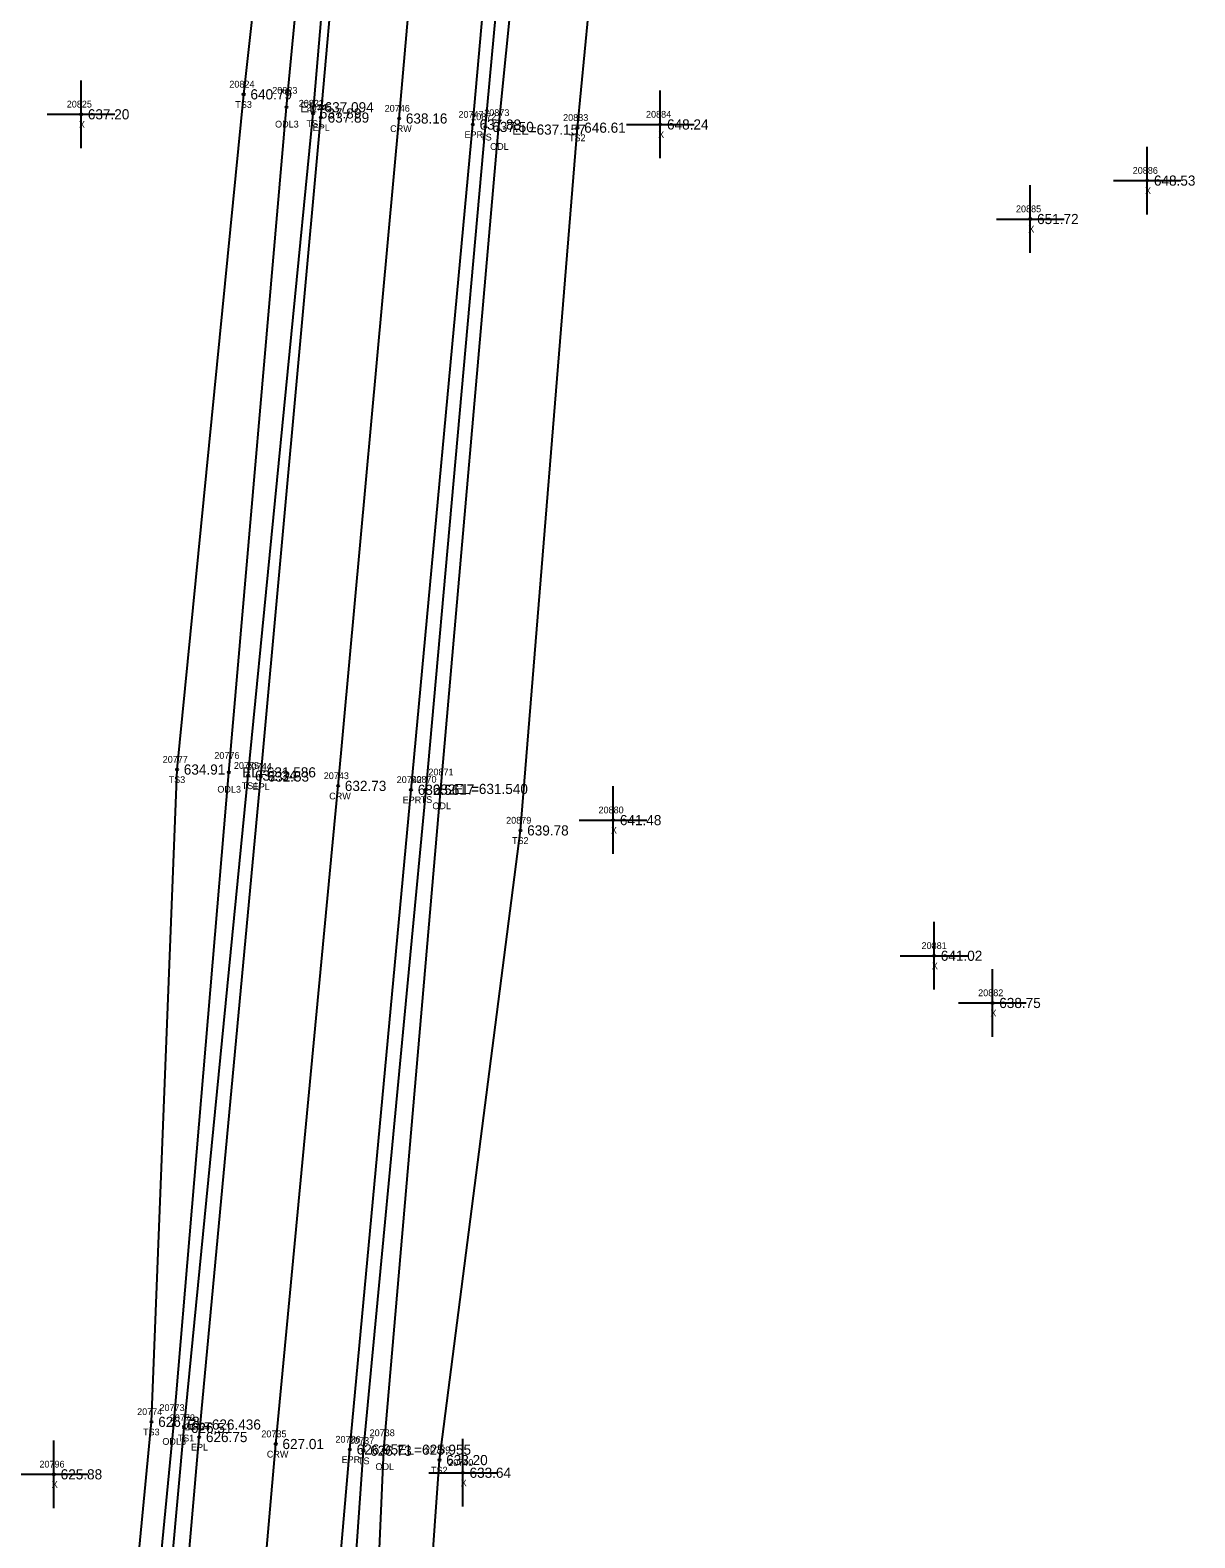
# Model space of a CAD drawing. Extents: x 1695443 to 1696344, y 1087542 to 1090645.
# Drawn here: x 1695816.3 to 1695988.4, y 1090201.9 to 1090424.7 of the extents above; entities that cross this region are included whole.
import ezdxf

# ---------------------------------------------------------------- set-up
doc = ezdxf.new("R2010")
doc.units = 0
for name, color, linetype in [('RD_DTM_BkLn1', 7, 'Continuous'), ('RD_DTM_BkLn2', 7, 'Continuous'), ('RD_DTM_BkLn_txCode', 7, 'Continuous'), ('RD_EX_H2O', 7, 'Continuous'), ('RD_EX_H2O_txCode', 7, 'Continuous'), ('RD_EX_Misc', 7, 'Continuous'), ('RD_EX_Misc_txCode', 7, 'Continuous'), ('RD_EX_Road', 7, 'Continuous'), ('RD_EX_Road_txCode', 7, 'Continuous'), ('RD_EX_TX_H2O_ELEV', 7, 'Continuous'), ('RD_EX_TX_Misc_ELEV', 7, 'Continuous'), ('RD_EX_TX_Road_ELEV', 7, 'Continuous'), ('RD_HC_Survey_ELEV', 7, 'Continuous'), ('RD_HC_Survey_txCode', 7, 'Continuous'), ('RD_SMD_Locator', 7, 'Continuous')]:
    doc.layers.add(name, color=color, linetype=linetype)

msp = doc.modelspace()

# ---------------------------------------------------------------- linework, layer by layer
at = {"layer": 'RD_DTM_BkLn1'}
msp.add_lwpolyline([(1695813.78, 1089148.1), (1695785.55, 1089189.03), (1695758.89, 1089235.87), (1695740.64, 1089279.02), (1695725.17, 1089334.02), (1695718.27, 1089382.65), (1695717.41, 1089435.13), (1695722.03, 1089482.62), (1695732.64, 1089534.75), (1695759.85, 1089631.43), (1695787.11, 1089727.89), (1695798.89, 1089774.41), (1695810.31, 1089824.5), (1695818.49, 1089870.61), (1695825.85, 1089922.33), (1695831.69, 1089976.57), (1695835.49, 1090019.27), (1695844.06, 1090117.91), (1695852.56, 1090215.73), (1695861.78, 1090313.02), (1695870.8, 1090411.68), (1695879.44, 1090510.15), (1695888.04, 1090606.94)], dxfattribs=at)
at = {"layer": 'RD_DTM_BkLn2'}
for points in [[(1695816.55, 1089985.57), (1695822.06, 1090019.33), (1695830.08, 1090118.98), (1695839.03, 1090218.11), (1695848.5, 1090314.54), (1695858.08, 1090412.43), (1695866.47, 1090510.6), (1695872.4, 1090582.09), (1695875.15, 1090613.95)], [(1695859.8, 1090070.52), (1695855.89, 1090074.82), (1695858.76, 1090117.78), (1695865.52, 1090214.74), (1695874.78, 1090312.49), (1695883.57, 1090410.43), (1695892.81, 1090510.92), (1695900.47, 1090609.03)], [(1695859.8, 1090070.52), (1695863.31, 1090073.64), (1695869.86, 1090116.28), (1695876.76, 1090213.36), (1695888.73, 1090306.44), (1695897.16, 1090410.32), (1695906.91, 1090511.46), (1695912.67, 1090607.68)], [(1695816.55, 1089985.57), (1695816.58, 1090019.89), (1695824.64, 1090119.16), (1695834.2, 1090219.01), (1695837.98, 1090315.44), (1695847.83, 1090415.25), (1695858.61, 1090512.14), (1695862.95, 1090562.02), (1695858.41, 1090574.71)]]:
    msp.add_lwpolyline(points, dxfattribs=at)
at = {"layer": 'RD_EX_H2O'}
for points in [[(1695860.52, 1090075.19), (1695864.26, 1090116.99), (1695868.56, 1090214.89), (1695876.96, 1090312.57), (1695885.5, 1090410.04), (1695895.53, 1090510.16), (1695905.88, 1090602.7), (1695906.59, 1090606.36)], [(1695816.55, 1089985.57), (1695820.09, 1090019.62), (1695827.87, 1090118.57), (1695837.5, 1090218.61), (1695845.63, 1090315.02), (1695854.17, 1090413.34), (1695863.46, 1090511.07), (1695865.97, 1090562.3), (1695858.41, 1090574.71)]]:
    msp.add_lwpolyline(points, dxfattribs=at)
at = {"layer": 'RD_EX_Misc'}
for p, q in [((1695823.8, 1090407.3), (1695823.8, 1090417.3)), ((1695909.4, 1090405.8), (1695909.4, 1090415.8)), ((1695818.8, 1090412.3), (1695828.8, 1090412.3)), ((1695904.4, 1090410.8), (1695914.4, 1090410.8)), ((1695981.36, 1090397.5), (1695981.36, 1090407.5)), ((1695964.09, 1090391.82), (1695964.09, 1090401.82)), ((1695976.36, 1090402.5), (1695986.36, 1090402.5)), ((1695959.09, 1090396.82), (1695969.09, 1090396.82)), ((1695902.43, 1090302.96), (1695902.43, 1090312.96)), ((1695897.43, 1090307.96), (1695907.43, 1090307.96)), ((1695949.86, 1090282.91), (1695949.86, 1090292.91)), ((1695944.86, 1090287.91), (1695954.86, 1090287.91)), ((1695958.5, 1090275.93), (1695958.5, 1090285.93)), ((1695953.5, 1090280.93), (1695963.5, 1090280.93)), ((1695880.21, 1090206.48), (1695880.21, 1090216.48)), ((1695819.78, 1090206.25), (1695819.78, 1090216.25)), ((1695814.78, 1090211.25), (1695824.78, 1090211.25)), ((1695875.21, 1090211.48), (1695885.21, 1090211.48))]:
    msp.add_line(p, q, dxfattribs=at)
at = {"layer": 'RD_EX_Road'}
for points in [[(1695813.78, 1089148.1), (1695805.56, 1089142.08), (1695776.44, 1089183.94), (1695749.27, 1089231.88), (1695730.49, 1089275.72), (1695714.87, 1089332.12), (1695707.87, 1089381.72), (1695706.58, 1089435.34), (1695711.58, 1089484.26), (1695722.15, 1089537.59), (1695749.04, 1089634.88), (1695776.11, 1089730.43), (1695788.13, 1089777.42), (1695798.89, 1089826.76), (1695807.1, 1089870.03), (1695814.71, 1089923.3), (1695820.51, 1089978.16), (1695824.04, 1090019.79), (1695832.76, 1090119.06), (1695841.25, 1090216.76), (1695850.36, 1090314.41), (1695859.24, 1090411.82), (1695868.09, 1090511.63), (1695876.75, 1090608.38)], [(1695728.69, 1089383.6), (1695727.9, 1089434.83), (1695732.68, 1089480.1), (1695743.4, 1089531.84), (1695770.35, 1089628.36), (1695797.63, 1089725.22), (1695809.49, 1089772.37), (1695818.34, 1089811.57), (1695820.65, 1089823.41), (1695822.99, 1089835.26), (1695829.18, 1089869.37), (1695836.32, 1089920.97), (1695842.44, 1089975.46), (1695846.49, 1090018.55), (1695849.32, 1090055.39), (1695850.91, 1090072.92), (1695855.09, 1090117.49), (1695863.53, 1090214.93), (1695872.56, 1090312.44), (1695881.69, 1090410.78), (1695890.45, 1090509.3), (1695899.01, 1090605.4)]]:
    msp.add_lwpolyline(points, dxfattribs=at)
at = {"layer": 'RD_SMD_Locator'}
for centre in [(1695847.83, 1090415.25), (1695854.17, 1090413.34), (1695858.08, 1090412.43), (1695823.8, 1090412.3), (1695859.24, 1090411.82), (1695870.8, 1090411.68), (1695881.69, 1090410.78), (1695883.57, 1090410.43), (1695897.16, 1090410.32), (1695909.4, 1090410.8), (1695885.5, 1090410.04), (1695981.36, 1090402.5), (1695964.09, 1090396.82), (1695837.98, 1090315.44), (1695845.63, 1090315.02), (1695848.5, 1090314.54), (1695850.36, 1090314.41), (1695861.78, 1090313.02), (1695872.56, 1090312.44), (1695874.78, 1090312.49), (1695876.96, 1090312.57), (1695902.43, 1090307.96), (1695888.73, 1090306.44), (1695949.86, 1090287.91), (1695958.5, 1090280.93), (1695834.2, 1090219.01), (1695837.5, 1090218.61), (1695839.03, 1090218.11), (1695841.25, 1090216.76), (1695852.56, 1090215.73), (1695863.53, 1090214.93), (1695865.52, 1090214.74), (1695868.56, 1090214.89), (1695876.76, 1090213.36), (1695819.78, 1090211.25), (1695880.21, 1090211.48)]:
    msp.add_circle(centre, 0.15, dxfattribs=at)

# ---------------------------------------------------------------- texts
at = {"layer": 'RD_DTM_BkLn_txCode'}
for s, p in [('20824', (1695845.71, 1090416.25)), ('TS3', (1695846.59, 1090413.25)), ('20822', (1695855.97, 1090413.43)), ('TS1', (1695857.12, 1090410.43)), ('20872', (1695881.45, 1090411.43)), ('20883', (1695895.04, 1090411.32)), ('TS', (1695882.78, 1090408.43)), ('TS2', (1695895.91, 1090408.32)), ('20777', (1695835.86, 1090316.44)), ('20775', (1695846.38, 1090315.54)), ('20870', (1695872.62, 1090313.49)), ('TS3', (1695836.74, 1090313.44)), ('TS1', (1695847.54, 1090312.54)), ('TS', (1695873.99, 1090310.49)), ('20879', (1695886.62, 1090307.44)), ('TS2', (1695887.49, 1090304.44)), ('20774', (1695832.08, 1090220.01)), ('20772', (1695836.91, 1090219.11)), ('TS3', (1695832.95, 1090217.01)), ('TS1', (1695838.07, 1090216.11)), ('20737', (1695863.4, 1090215.74)), ('20739', (1695874.64, 1090214.36)), ('TS', (1695864.72, 1090212.74)), ('TS2', (1695875.51, 1090211.36))]:
    msp.add_text(s, height=1, dxfattribs=at).set_placement(p)
at = {"layer": 'RD_EX_H2O_txCode'}
for s, p in [('20823', (1695852.05, 1090415.34)), ('20873', (1695883.38, 1090412.04)), ('ODL3', (1695852.47, 1090410.34)), ('ODL', (1695884.25, 1090407.04)), ('20776', (1695843.49, 1090317.02)), ('20871', (1695875.13, 1090314.57)), ('ODL3', (1695843.94, 1090312.02)), ('ODL', (1695875.72, 1090309.57)), ('20773', (1695835.38, 1090220.61)), ('ODL3', (1695835.81, 1090215.61)), ('20738', (1695866.44, 1090216.89)), ('ODL', (1695867.31, 1090211.89))]:
    msp.add_text(s, height=1, dxfattribs=at).set_placement(p)
at = {"layer": 'RD_EX_Misc_txCode'}
for s, p in [('20825', (1695821.68, 1090413.3)), ('20884', (1695907.29, 1090411.8)), ('X', (1695823.48, 1090410.3)), ('X', (1695909.09, 1090408.8)), ('20886', (1695979.22, 1090403.5)), ('X', (1695981.04, 1090400.5)), ('20885', (1695961.97, 1090397.82)), ('X', (1695963.78, 1090394.82)), ('20880', (1695900.27, 1090308.96)), ('X', (1695902.11, 1090305.96)), ('20881', (1695948.02, 1090288.91)), ('X', (1695949.54, 1090285.91)), ('20882', (1695956.38, 1090281.93)), ('X', (1695958.19, 1090278.93)), ('20796', (1695817.64, 1090212.25)), ('20740', (1695878.05, 1090212.48)), ('X', (1695819.46, 1090209.25)), ('X', (1695879.9, 1090209.48))]:
    msp.add_text(s, height=1, dxfattribs=at).set_placement(p)
at = {"layer": 'RD_EX_Road_txCode'}
for s, p in [('20745', (1695857.12, 1090412.82)), ('20747', (1695879.57, 1090411.78)), ('EPL', (1695858.03, 1090409.82)), ('EPR', (1695880.46, 1090408.78)), ('20744', (1695848.25, 1090315.41)), ('EPL', (1695849.16, 1090312.41)), ('20742', (1695870.44, 1090313.44)), ('EPR', (1695871.33, 1090310.44)), ('20734', (1695839.13, 1090217.76)), ('20736', (1695861.39, 1090215.93)), ('EPL', (1695840.04, 1090214.76)), ('EPR', (1695862.3, 1090212.93))]:
    msp.add_text(s, height=1, dxfattribs=at).set_placement(p)
at = {"layer": 'RD_EX_TX_H2O_ELEV'}
for s, p in [('EL=637.094', (1695856.17, 1090412.59)), ('EL=637.157', (1695887.5, 1090409.29)), ('EL=631.586', (1695847.63, 1090314.27)), ('EL=631.540', (1695878.96, 1090311.82)), ('EL=626.436', (1695839.5, 1090217.86)), ('EL=625.955', (1695870.56, 1090214.14))]:
    msp.add_text(s, height=1.5, dxfattribs=at).set_placement(p)
at = {"layer": 'RD_EX_TX_Misc_ELEV'}
for s, p in [('640.79', (1695848.83, 1090414.5)), ('637.20', (1695824.8, 1090411.55)), ('637.89', (1695859.08, 1090411.68)), ('637.50', (1695884.57, 1090409.68)), ('646.61', (1695898.16, 1090409.57)), ('648.24', (1695910.4, 1090410.05)), ('648.53', (1695982.36, 1090401.75)), ('651.72', (1695965.09, 1090396.07)), ('634.91', (1695838.98, 1090314.69)), ('632.34', (1695849.5, 1090313.79)), ('632.17', (1695875.78, 1090311.74)), ('641.48', (1695903.43, 1090307.21)), ('639.78', (1695889.73, 1090305.69)), ('641.02', (1695950.86, 1090287.16)), ('638.75', (1695959.5, 1090280.18)), ('626.78', (1695835.2, 1090218.26)), ('626.51', (1695840.03, 1090217.36)), ('626.73', (1695866.52, 1090213.99)), ('625.88', (1695820.78, 1090210.5)), ('633.20', (1695877.76, 1090212.61)), ('633.64', (1695881.21, 1090210.73))]:
    msp.add_text(s, height=1.5, dxfattribs=at).set_placement(p)
at = {"layer": 'RD_EX_TX_Road_ELEV'}
for s, p in [('637.89', (1695860.24, 1090411.07)), ('637.88', (1695882.69, 1090410.03)), ('632.53', (1695851.36, 1090313.66)), ('632.56', (1695873.56, 1090311.69)), ('626.75', (1695842.25, 1090216.01)), ('626.95', (1695864.53, 1090214.18))]:
    msp.add_text(s, height=1.5, dxfattribs=at).set_placement(p)
at = {"layer": 'RD_HC_Survey_ELEV'}
for s, p in [('638.16', (1695871.8, 1090410.93)), ('632.73', (1695862.78, 1090312.27)), ('627.01', (1695853.56, 1090214.98))]:
    msp.add_text(s, height=1.5, dxfattribs=at).set_placement(p)
at = {"layer": 'RD_HC_Survey_txCode'}
for s, p in [('20746', (1695868.66, 1090412.68)), ('CRW', (1695869.48, 1090409.68)), ('20743', (1695859.66, 1090314.02)), ('CRW', (1695860.47, 1090311.02)), ('20735', (1695850.44, 1090216.73)), ('CRW', (1695851.25, 1090213.73))]:
    msp.add_text(s, height=1, dxfattribs=at).set_placement(p)

doc.saveas('drawing.dxf')
